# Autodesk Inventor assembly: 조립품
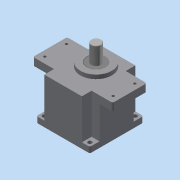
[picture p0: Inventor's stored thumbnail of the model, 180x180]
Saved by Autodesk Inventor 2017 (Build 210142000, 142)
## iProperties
Part Number: 조립품
Material: 일반
Document SubType Name: Assembly
Designer: user
Author: user
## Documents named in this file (10)
- C:\Users\user\Desktop\700116V1007\조립품.iam
- C:\Users\user\Desktop\700116V1007\메인 축.ipt
- C:\Users\user\Desktop\700116V1007\베어링 608.ipt
- C:\Users\user\Desktop\700116V1007\베어링 6003.ipt
- C:\Users\user\Desktop\700116V1007\본체.ipt
- C:\Users\user\Desktop\700116V1007\볼트 M4.ipt
- C:\Users\user\Desktop\700116V1007\서브 축.ipt
- C:\Users\user\Desktop\700116V1007\오일 실 8 22 7.ipt
- C:\Users\user\Desktop\700116V1007\오일 실 17 32 8.ipt
- C:\Users\user\Desktop\700116V1007\커버.ipt
